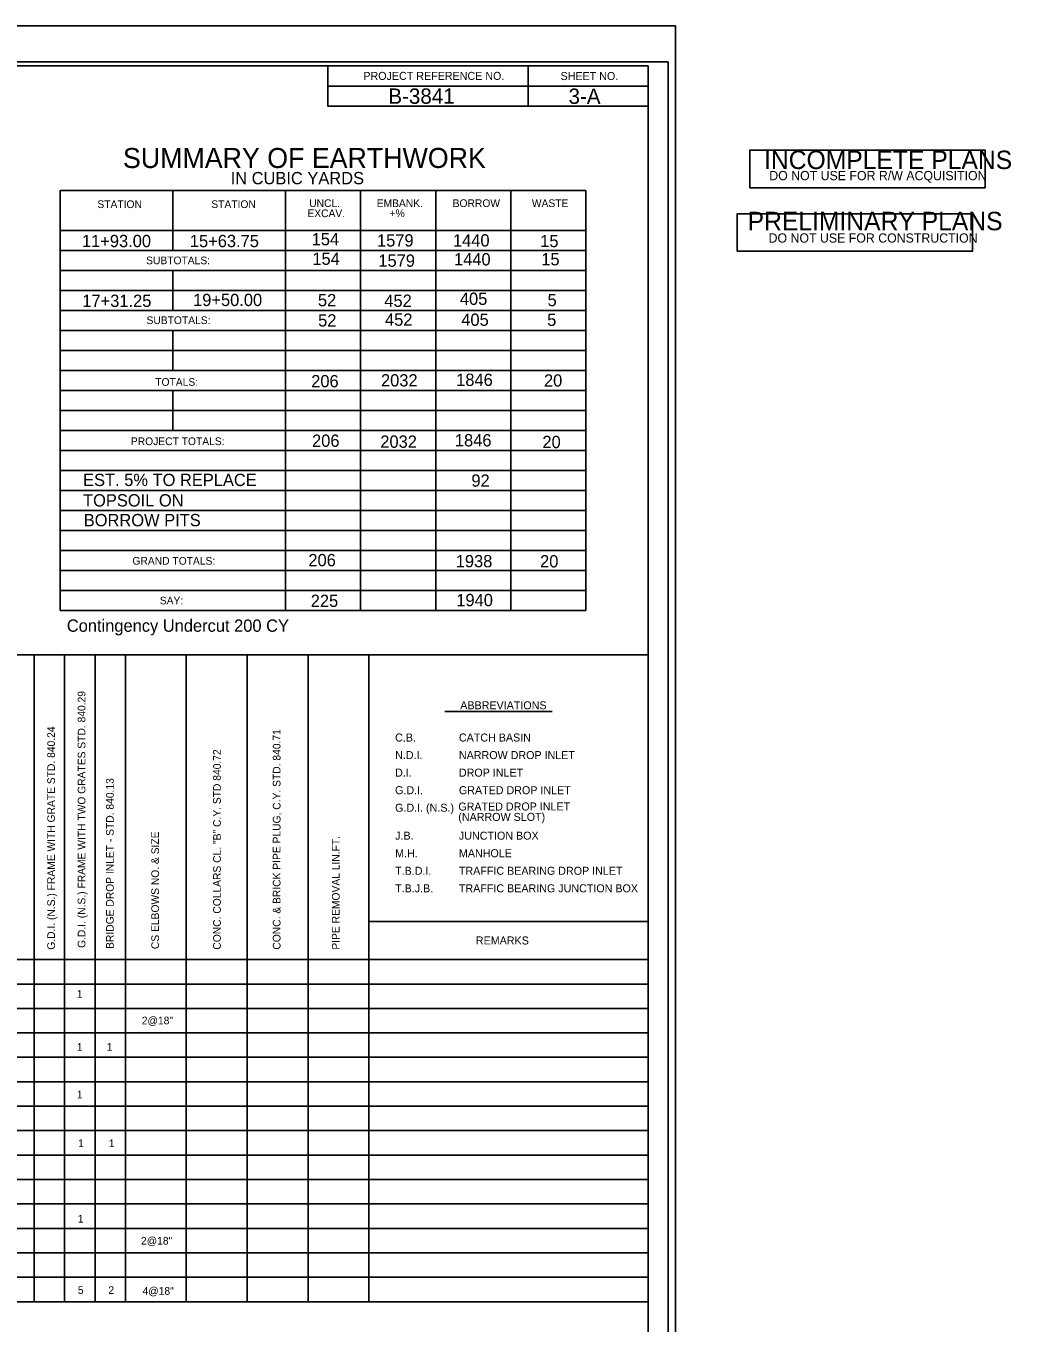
# Model space of a CAD drawing. Extents: x 573359 to 575895, y -54193 to -50493.
# Drawn here: x 574880 to 575496, y -51303 to -50493 of the extents above; entities that cross this region are included whole.
import ezdxf

# ---------------------------------------------------------------- set-up
doc = ezdxf.new("R2010")
doc.units = 0
for name, color, linetype in [('Prop Dimension Text', 7, 'Continuous'), ('Sheet Cutting Line CELL', 7, 'Continuous'), ('Sheet Pipe Summary CELL', 7, 'Continuous'), ('Sheet Pipe Summary Grid CELL', 7, 'Continuous'), ('Sheet Plot Border Inside CELL', 7, 'Continuous'), ('Sheet Plot Border Outside CELL', 7, 'Continuous'), ('Sheet Sticker Incomplete CELL', 7, 'Continuous'), ('Sheet Sticker Preliminary CELL', 7, 'Continuous'), ('Sheet Summary Combination CELL', 7, 'Continuous'), ('Sheet Summary Combination Grid CELL', 7, 'Continuous')]:
    doc.layers.add(name, color=color, linetype=linetype)

msp = doc.modelspace()

# ---------------------------------------------------------------- linework, layer by layer
at = {"layer": 'Sheet Cutting Line CELL'}
msp.add_line((575286.01, -50493.3), (573602.01, -50493.3), dxfattribs=at)
at = {"layer": 'Sheet Pipe Summary CELL'}
msp.add_line((575209.14, -50921.52), (575142.14, -50921.52), dxfattribs=at)
at = {"layer": 'Sheet Pipe Summary Grid CELL'}
for p, q in [((575269.01, -50886), (573769.01, -50886.1)), ((574885.63, -51290.2), (574885.61, -50886.04)), ((574904.63, -51290.2), (574904.61, -50886.04)), ((574923.63, -51290.2), (574923.61, -50886.04)), ((574942.63, -51290.2), (574942.61, -50886.03)), ((574980.63, -51290.2), (574980.61, -50886.03)), ((574980.63, -51290.2), (574980.61, -50886.03)), ((575018.63, -51290.2), (575018.61, -50886.03)), ((575018.63, -51290.2), (575018.61, -50886.03)), ((575056.63, -51290.2), (575056.61, -50886.03)), ((575056.63, -51290.2), (575056.61, -50886.03)), ((575094.63, -51290.2), (575094.61, -50886.03)), ((575094.63, -51290.2), (575094.61, -50886.03)), ((575269.01, -51052.57), (575094.62, -51052.57)), ((575269.01, -51076.4), (573769.01, -51076.4)), ((575269.01, -51091.7), (573769.01, -51091.7)), ((575269.01, -51106.95), (573769.01, -51106.95)), ((575269.01, -51122.2), (573769.01, -51122.2)), ((575269.01, -51137.5), (573769.01, -51137.5)), ((575269.01, -51152.75), (573769.01, -51152.75)), ((575269.01, -51168.05), (573769.01, -51168.05)), ((575269.01, -51183.3), (573769.01, -51183.3)), ((575269.01, -51198.55), (573769.01, -51198.55)), ((575269.01, -51213.85), (573769.01, -51213.85)), ((575269.01, -51213.85), (573769.01, -51213.85)), ((575269.01, -51229.1), (573769.01, -51229.1)), ((575269.01, -51244.4), (573769.01, -51244.4)), ((575269.01, -51259.65), (573769.01, -51259.65)), ((575269.01, -51274.9), (573769.01, -51274.9)), ((575269.01, -51274.9), (573769.01, -51274.9)), ((575269.01, -51290.2), (573769.01, -51290.2)), ((575269.01, -51290.2), (573769.01, -51290.2))]:
    msp.add_line(p, q, dxfattribs=at)
at = {"layer": 'Sheet Plot Border Inside CELL'}
msp.add_lwpolyline([(575281.51, -50515.75), (573615.01, -50515.75), (573615.01, -51570.85), (575281.51, -51570.85)], close=True, dxfattribs=at)
at = {"layer": 'Sheet Plot Border Outside CELL'}
msp.add_lwpolyline([(575286.01, -50493.3), (573602.01, -50493.3), (573602.01, -51593.3), (575286.01, -51593.3)], close=True, dxfattribs=at)
at = {"layer": 'Sheet Sticker Incomplete CELL'}
msp.add_lwpolyline([(575332.43, -50594.39), (575332.43, -50570.89), (575479.43, -50570.89), (575479.43, -50594.39)], close=True, dxfattribs=at)
at = {"layer": 'Sheet Sticker Preliminary CELL'}
msp.add_lwpolyline([(575324.6, -50634.07), (575324.6, -50610.57), (575471.6, -50610.57), (575471.6, -50634.07)], close=True, dxfattribs=at)
at = {"layer": 'Sheet Summary Combination CELL'}
for p, q in [((575194.01, -50518.35), (575194.01, -50543.35)), ((575068.96, -50530.85), (575269.01, -50530.85)), ((575068.96, -50543.35), (575269.01, -50543.35)), ((574996.28, -50596.06), (574996.28, -50596.06)), ((575002.53, -50596.16), (575002.53, -50596.16)), ((575011.58, -50595.96), (575011.58, -50595.96)), ((575017.18, -50596.06), (575017.18, -50596.06))]:
    msp.add_line(p, q, dxfattribs=at)
for points in [[(575269.01, -50518.3), (573769.01, -50518.3), (573769.01, -51568.3), (575269.01, -51568.3)], [(575068.96, -50518.3), (575269.01, -50518.3), (575269.01, -50543.35), (575068.96, -50543.35)]]:
    msp.add_lwpolyline(points, close=True, dxfattribs=at)
at = {"layer": 'Sheet Summary Combination Grid CELL'}
for p, q in [((574901.93, -50596.01), (575230.18, -50596.01)), ((574901.93, -50596.01), (574901.93, -50733.51)), ((574972.28, -50596.01), (574972.28, -50633.51)), ((575042.58, -50596.01), (575042.58, -50733.51)), ((575089.48, -50596.01), (575089.48, -50733.51)), ((575136.38, -50596.01), (575136.38, -50733.51)), ((575183.28, -50596.01), (575183.28, -50733.51)), ((575230.18, -50596.01), (575230.18, -50733.51)), ((574901.93, -50621.01), (575230.18, -50621.01)), ((574901.93, -50633.51), (575230.18, -50633.51)), ((574901.93, -50646.01), (575230.18, -50646.01)), ((574972.28, -50646.01), (574972.28, -50671.01)), ((574901.93, -50658.51), (575230.18, -50658.51)), ((574901.93, -50671.01), (575230.18, -50671.01)), ((574901.93, -50683.51), (575230.18, -50683.51)), ((574972.28, -50683.51), (574972.28, -50708.51)), ((574901.93, -50696.01), (575230.18, -50696.01)), ((574901.93, -50708.51), (575230.18, -50708.51)), ((574901.93, -50721.01), (575230.18, -50721.01)), ((574972.28, -50721.01), (574972.28, -50733.51)), ((574901.93, -50733.51), (575230.18, -50733.51)), ((574901.93, -50733.51), (574901.93, -50858.51)), ((574972.28, -50733.51), (574972.28, -50746.01)), ((575042.58, -50733.51), (575042.58, -50858.51)), ((575089.48, -50733.51), (575089.48, -50858.51)), ((575136.38, -50733.51), (575136.38, -50858.51)), ((575183.28, -50733.51), (575183.28, -50858.51)), ((575230.18, -50733.51), (575230.18, -50858.51)), ((574901.93, -50746.01), (575230.18, -50746.01)), ((574901.93, -50758.51), (575230.18, -50758.51)), ((574901.93, -50771.01), (575230.18, -50771.01)), ((574901.93, -50783.51), (575230.18, -50783.51)), ((574901.93, -50796.01), (575230.18, -50796.01)), ((574901.93, -50796.01), (575230.18, -50796.01)), ((574901.93, -50808.51), (575230.18, -50808.51)), ((574901.93, -50808.51), (575230.18, -50808.51)), ((574901.93, -50821.01), (575230.18, -50821.01)), ((574901.93, -50821.01), (575230.18, -50821.01)), ((574901.93, -50833.51), (575230.18, -50833.51)), ((574901.93, -50846.01), (575230.18, -50846.01)), ((574901.93, -50858.51), (575230.18, -50858.51))]:
    msp.add_line(p, q, dxfattribs=at)

# ---------------------------------------------------------------- texts
at = {"layer": 'Prop Dimension Text'}
for s, height, p in [('B-3841', 9.6, (575106.77, -50541.93)), ('3-A', 9.6, (575219.29, -50542.01)), ('11+93.00', 7.68, (574915.46, -50631.47)), ('15+63.75', 7.68, (574982.83, -50631.47)), ('154', 7.68, (575058.89, -50630.3)), ('1579', 7.68, (575099.7, -50631.08)), ('1440', 7.68, (575147.13, -50631.08)), ('15', 7.68, (575201.62, -50631.47)), ('154', 7.68, (575059.33, -50642.52)), ('1440', 7.68, (575147.79, -50642.88)), ('15', 7.68, (575202.27, -50642.84)), ('1579', 7.68, (575100.54, -50643.72)), ('405', 7.68, (575151.45, -50667.55)), ('17+31.25', 7.68, (574915.68, -50668.81)), ('19+50.00', 7.68, (574984.84, -50668.26)), ('52', 7.68, (575062.81, -50668.39)), ('452', 7.68, (575104.28, -50668.78)), ('5', 7.68, (575206.21, -50668.31)), ('52', 7.68, (575062.92, -50681.03)), ('452', 7.68, (575104.7, -50680.57)), ('405', 7.68, (575152.33, -50680.61)), ('5', 7.68, (575205.96, -50680.71)), ('206', 7.68, (575058.61, -50719)), ('2032', 7.68, (575102.19, -50718.48)), ('1846', 7.68, (575149.13, -50718.16)), ('20', 7.68, (575203.96, -50718.58)), ('206', 7.68, (575059.13, -50756.19)), ('2032', 7.68, (575101.77, -50756.77)), ('1846', 7.68, (575148.32, -50755.92)), ('20', 7.68, (575202.98, -50756.99)), ('EST. 5% TO REPLACE ', 7.68, (574916.16, -50780.67)), ('92', 7.68, (575158.65, -50781.08)), ('TOPSOIL ON', 7.68, (574916.13, -50793.44)), ('BORROW PITS', 7.68, (574916.58, -50805.8)), ('206', 7.68, (575056.85, -50830.78)), ('1938', 7.68, (575148.86, -50831.43)), ('20', 7.68, (575201.52, -50831.51)), ('225', 7.68, (575058.32, -50856.19)), ('1940', 7.68, (575149.23, -50855.74)), ('Contingency Undercut 200 CY', 7.68, (574906, -50871.7)), ('1', 4.8, (574912.28, -51100.26)), ('2@18"', 4.8, (574952.82, -51116.91)), ('1', 4.8, (574912.28, -51133.42)), ('1', 4.8, (574930.9, -51133.42)), ('1', 4.8, (574912.28, -51163.17)), ('1', 4.8, (574913.02, -51193.57)), ('1', 4.8, (574932.2, -51193.57)), ('1', 4.8, (574912.83, -51240.7)), ('2@18"', 4.8, (574952.32, -51254.47)), ('5', 4.8, (574912.88, -51285.28)), ('2', 4.8, (574931.94, -51285.28)), ('4@18"', 4.8, (574953.28, -51285.81))]:
    msp.add_text(s, height=height, dxfattribs=at).set_placement(p)
at = {"layer": 'Sheet Pipe Summary CELL'}
for s, height, rotation, p in [('G.D.I. (N.S.) FRAME WITH TWO GRATES STD. 840.29', 4.8, 90, (574917.6, -51069.18)), ('G.D.I. (N.S.) FRAME WITH GRATE STD. 840.24', 4.8, 90, (574898.59, -51070.29)), ('CONC. & BRICK PIPE PLUG, C.Y. STD. 840.71', 4.8, 90, (575039.43, -51070.24)), ('CONC. COLLARS CL. "B" C.Y. STD 840.72', 4.8, 90, (575002.16, -51070.24)), ('BRIDGE DROP INLET - STD. 840.13', 4.8, 90, (574935.29, -51069.78)), ('GRATED DROP INLET', 5.0001, 0.02739, (575150.47, -50983.35)), ('(NARROW SLOT)', 5.0001, 0.02739, (575150.47, -50989.85)), ('CS ELBOWS NO. & SIZE', 4.8, 90, (574963.56, -51069.9)), ('PIPE REMOVAL LIN.FT.', 4.8, 90, (575076.37, -51070.24))]:
    msp.add_text(s, height=height, rotation=rotation, dxfattribs=at).set_placement(p)
for s, height, p in [('ABBREVIATIONS', 5.0001, (575151.69, -50920.12)), ('C.B.', 5, (575111, -50940.25)), ('CATCH BASIN', 5.0001, (575150.84, -50940.25)), ('N.D.I.', 5, (575111, -50951.21)), ('NARROW DROP INLET', 5.0001, (575150.84, -50951.21)), ('D.I.', 5, (575111, -50962.17)), ('DROP INLET', 5, (575150.84, -50962.17)), ('G.D.I.', 5, (575111, -50973.14)), ('GRATED DROP INLET', 5.0001, (575150.84, -50973.14)), ('G.D.I. (N.S.)', 5.0001, (575111, -50984.1)), ('J.B.', 5, (575111, -51001.55)), ('JUNCTION BOX', 5.0001, (575150.84, -51001.55)), ('M.H.', 5, (575111, -51012.52)), ('MANHOLE', 5, (575150.84, -51012.52)), ('T.B.D.I.', 5, (575111, -51023.48)), ('TRAFFIC BEARING DROP INLET', 5.0001, (575150.84, -51023.48)), ('T.B.J.B.', 5, (575111, -51034.44)), ('TRAFFIC BEARING JUNCTION BOX', 5.0001, (575150.84, -51034.44)), ('REMARKS', 5, (575161.44, -51067.02))]:
    msp.add_text(s, height=height, dxfattribs=at).set_placement(p)
at = {"layer": 'Sheet Sticker Incomplete CELL'}
for s, height, p in [('INCOMPLETE PLANS', 11.52, (575341.38, -50582.69)), ('DO NOT USE FOR R/W ACQUISITION', 5.76, (575344.63, -50589.64))]:
    msp.add_text(s, height=height, dxfattribs=at).set_placement(p)
at = {"layer": 'Sheet Sticker Preliminary CELL'}
for s, height, p in [('PRELIMINARY PLANS', 11.52, (575331.1, -50620.92)), ('DO NOT USE FOR CONSTRUCTION', 5.76, (575344.2, -50628.62))]:
    msp.add_text(s, height=height, dxfattribs=at).set_placement(p)
at = {"layer": 'Sheet Summary Combination CELL'}
for s, height, p in [('PROJECT REFERENCE NO.', 5.0001, (575091.16, -50527)), ('SHEET NO.', 5, (575214.31, -50527.1)), ('STATION', 4.8, (574925.08, -50607.05)), ('STATION', 4.8, (574996.22, -50607.03)), ('UNCL.', 4.8, (575057.37, -50606.41)), ('EMBANK.', 4.8, (575099.48, -50606.41)), ('BORROW', 4.8, (575146.93, -50606.41)), ('WASTE', 4.8, (575196.38, -50606.41)), ('EXCAV.', 4.8, (575056.22, -50612.71)), ('+%', 4.8, (575107.54, -50612.71)), ('SUBTOTALS:', 4.8, (574955.51, -50642.15)), ('SUBTOTALS:', 4.8, (574955.77, -50679.5)), ('TOTALS:', 4.8, (574961.22, -50718.06)), ('PROJECT TOTALS:', 4.8, (574946, -50755.11)), ('GRAND TOTALS:', 4.8, (574946.98, -50829.79)), ('SAY:', 4.8, (574964.06, -50854.6))]:
    msp.add_text(s, height=height, dxfattribs=at).set_placement(p)
for s, height, p in [('SUMMARY OF EARTHWORK', 12.5001, (574941.06, -50582.04)), ('IN CUBIC YARDS', 7.6766, (575008.31, -50592.2))]:
    msp.add_text(s, height=height, rotation=0.01193, dxfattribs=at).set_placement(p)

doc.saveas('drawing.dxf')
